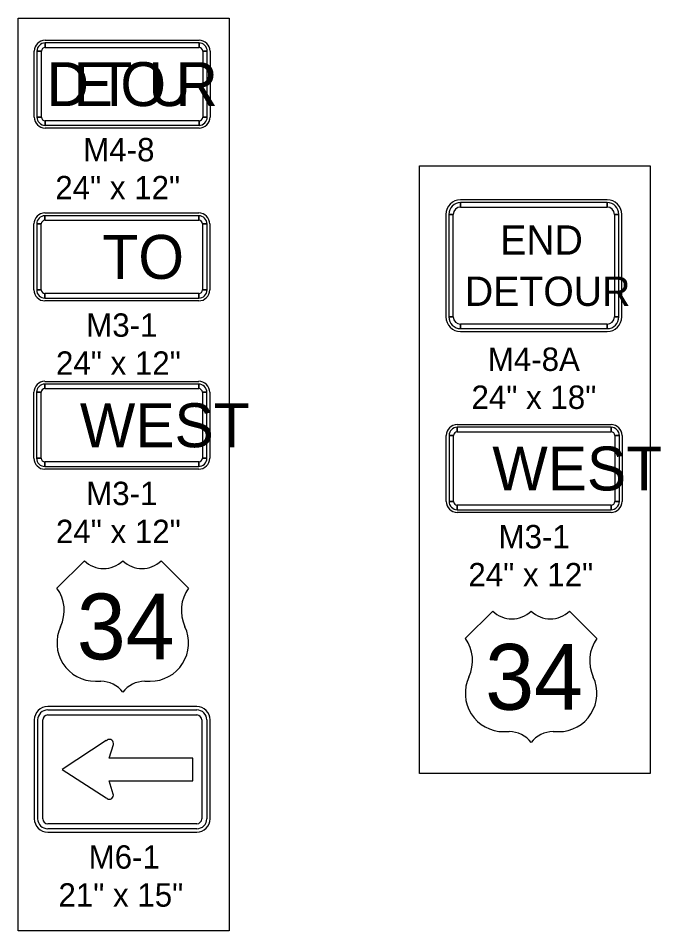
# Model space of a CAD drawing. Extents: x 10133 to 81668, y 6132 to 11018.
# Drawn here: x 11743.4 to 11963.1, y 6708.9 to 7021.1 of the extents above; entities that cross this region are included whole.
import ezdxf

# ---------------------------------------------------------------- set-up
doc = ezdxf.new("R2010")
doc.units = 0
for name, color, linetype in [('dsnTextFinalPlan', 7, 'Continuous'), ('Level 10', 7, 'Continuous'), ('Level 4', 7, 'Continuous'), ('Level 5', 7, 'Continuous')]:
    doc.layers.add(name, color=color, linetype=linetype)

msp = doc.modelspace()

# ---------------------------------------------------------------- linework, layer by layer
at = {"layer": 'dsnTextFinalPlan'}
for points in [[(11743.36, 7021.13), (11815.43, 7021.13), (11815.43, 6708.91), (11743.36, 6708.91)], [(11743.36, 7021.13), (11815.43, 7021.13), (11815.43, 6708.91), (11743.36, 6708.91)], [(11880.59, 6970.58), (11959.41, 6970.58), (11959.41, 6762.68), (11880.59, 6762.68)]]:
    msp.add_lwpolyline(points, close=True, dxfattribs=at)
at = {"layer": 'Level 10'}
for p, q in [((11752.57, 7013.62), (11805.18, 7013.62)), ((11752.57, 7013.62), (11805.18, 7013.62)), ((11752.57, 7011.12), (11752.57, 7012.68)), ((11752.57, 7011.12), (11752.57, 7012.68)), ((11805.18, 7012.68), (11805.18, 7011.12)), ((11805.18, 7012.68), (11805.18, 7011.12)), ((11748.81, 6987.31), (11748.81, 7009.86)), ((11748.81, 6987.31), (11748.81, 7009.86)), ((11749.75, 7009.86), (11751.32, 7009.86)), ((11749.75, 7009.86), (11751.32, 7009.86)), ((11806.43, 7009.86), (11808, 7009.86)), ((11806.43, 7009.86), (11808, 7009.86)), ((11808.94, 7009.86), (11808.94, 6987.31)), ((11808.94, 7009.86), (11808.94, 6987.31)), ((11751.32, 6987.31), (11749.75, 6987.31)), ((11751.32, 6987.31), (11749.75, 6987.31)), ((11752.57, 6984.5), (11752.57, 6986.06)), ((11752.57, 6984.5), (11752.57, 6986.06)), ((11805.18, 6986.06), (11805.18, 6984.5)), ((11805.18, 6986.06), (11805.18, 6984.5)), ((11808, 6987.31), (11806.43, 6987.31)), ((11808, 6987.31), (11806.43, 6987.31)), ((11805.18, 6983.56), (11752.57, 6983.56)), ((11805.18, 6983.56), (11752.57, 6983.56)), ((11944.74, 6959.04), (11894.63, 6959.04)), ((11894.63, 6956.53), (11894.63, 6958.04)), ((11944.74, 6958.04), (11894.63, 6958.04)), ((11894.63, 6958.04), (11894.63, 6956.53)), ((11894.63, 6956.53), (11944.74, 6956.53)), ((11944.74, 6956.53), (11944.74, 6958.04)), ((11944.74, 6958.04), (11944.74, 6956.53)), ((11752.48, 6954.5), (11805.09, 6954.5)), ((11752.48, 6954.5), (11805.09, 6954.5)), ((11752.48, 6952), (11752.48, 6953.56)), ((11752.48, 6952), (11752.48, 6953.56)), ((11805.09, 6953.56), (11805.09, 6952)), ((11805.09, 6953.56), (11805.09, 6952)), ((11889.62, 6954.03), (11889.62, 6918.95)), ((11890.63, 6954.03), (11890.63, 6918.95)), ((11892.13, 6954.03), (11890.63, 6954.03)), ((11890.63, 6954.03), (11892.13, 6954.03)), ((11892.13, 6918.95), (11892.13, 6954.03)), ((11947.25, 6954.03), (11948.75, 6954.03)), ((11947.25, 6954.03), (11947.25, 6918.95)), ((11948.75, 6954.03), (11947.25, 6954.03)), ((11948.75, 6918.95), (11948.75, 6954.03)), ((11949.75, 6918.95), (11949.75, 6954.03)), ((11748.72, 6928.19), (11748.72, 6950.74)), ((11748.72, 6928.19), (11748.72, 6950.74)), ((11749.66, 6950.74), (11751.22, 6950.74)), ((11749.66, 6950.74), (11751.22, 6950.74)), ((11806.34, 6950.74), (11807.91, 6950.74)), ((11806.34, 6950.74), (11807.91, 6950.74)), ((11808.85, 6950.74), (11808.85, 6928.19)), ((11808.85, 6950.74), (11808.85, 6928.19)), ((11751.22, 6928.19), (11749.66, 6928.19)), ((11751.22, 6928.19), (11749.66, 6928.19)), ((11752.48, 6925.38), (11752.48, 6926.94)), ((11752.48, 6925.38), (11752.48, 6926.94)), ((11805.09, 6926.94), (11805.09, 6925.38)), ((11805.09, 6926.94), (11805.09, 6925.38)), ((11807.91, 6928.19), (11806.34, 6928.19)), ((11807.91, 6928.19), (11806.34, 6928.19)), ((11805.09, 6924.44), (11752.48, 6924.44)), ((11805.09, 6924.44), (11752.48, 6924.44)), ((11890.63, 6918.95), (11892.13, 6918.95)), ((11892.13, 6918.95), (11890.63, 6918.95)), ((11947.25, 6918.95), (11948.75, 6918.95)), ((11948.75, 6918.95), (11947.25, 6918.95)), ((11944.74, 6916.45), (11894.63, 6916.45)), ((11894.63, 6916.45), (11894.63, 6914.94)), ((11894.63, 6914.94), (11894.63, 6916.45)), ((11944.74, 6916.45), (11944.74, 6914.94)), ((11944.74, 6914.94), (11944.74, 6916.45)), ((11894.63, 6914.94), (11944.74, 6914.94)), ((11894.63, 6913.94), (11944.74, 6913.94)), ((11752.45, 6896.89), (11805.07, 6896.89)), ((11752.45, 6896.89), (11805.07, 6896.89)), ((11752.45, 6894.39), (11752.45, 6895.95)), ((11752.45, 6894.39), (11752.45, 6895.95)), ((11805.07, 6895.95), (11805.07, 6894.39)), ((11805.07, 6895.95), (11805.07, 6894.39)), ((11748.7, 6870.59), (11748.7, 6893.14)), ((11748.7, 6870.59), (11748.7, 6893.14)), ((11749.64, 6893.14), (11751.2, 6893.14)), ((11749.64, 6893.14), (11751.2, 6893.14)), ((11806.32, 6893.14), (11807.89, 6893.14)), ((11806.32, 6893.14), (11807.89, 6893.14)), ((11808.82, 6893.14), (11808.82, 6870.59)), ((11808.82, 6893.14), (11808.82, 6870.59)), ((11893.49, 6882.11), (11946.1, 6882.11)), ((11889.73, 6855.8), (11889.73, 6878.35)), ((11890.67, 6878.35), (11892.24, 6878.35)), ((11893.49, 6879.6), (11893.49, 6881.17)), ((11946.1, 6881.17), (11946.1, 6879.6)), ((11947.35, 6878.35), (11948.92, 6878.35)), ((11949.86, 6878.35), (11949.86, 6855.8)), ((11751.2, 6870.59), (11749.64, 6870.59)), ((11751.2, 6870.59), (11749.64, 6870.59)), ((11752.45, 6867.77), (11752.45, 6869.33)), ((11752.45, 6867.77), (11752.45, 6869.33)), ((11805.07, 6869.33), (11805.07, 6867.77)), ((11805.07, 6869.33), (11805.07, 6867.77)), ((11807.89, 6870.59), (11806.32, 6870.59)), ((11807.89, 6870.59), (11806.32, 6870.59)), ((11805.07, 6866.83), (11752.45, 6866.83)), ((11805.07, 6866.83), (11752.45, 6866.83)), ((11892.24, 6855.8), (11890.67, 6855.8)), ((11893.49, 6852.98), (11893.49, 6854.55)), ((11946.1, 6854.55), (11946.1, 6852.98)), ((11948.92, 6855.8), (11947.35, 6855.8)), ((11946.1, 6852.04), (11893.49, 6852.04)), ((11804.39, 6785.6), (11753.42, 6785.6)), ((11804.39, 6785.6), (11753.42, 6785.6)), ((11753.43, 6784.46), (11804.4, 6784.46)), ((11753.43, 6784.46), (11804.4, 6784.46)), ((11753.43, 6782.74), (11804.4, 6782.74)), ((11753.43, 6782.74), (11804.4, 6782.74)), ((11748.84, 6781.02), (11748.84, 6747.24)), ((11748.84, 6781.02), (11748.84, 6747.24)), ((11750, 6747.24), (11750, 6781.02)), ((11750, 6747.24), (11750, 6781.02)), ((11751.72, 6747.24), (11751.72, 6781.02)), ((11751.72, 6747.24), (11751.72, 6781.02)), ((11806.12, 6781.02), (11806.12, 6747.24)), ((11806.12, 6781.02), (11806.12, 6747.24)), ((11807.84, 6781.02), (11807.84, 6747.24)), ((11807.84, 6781.02), (11807.84, 6747.24)), ((11808.97, 6747.24), (11808.97, 6781.02)), ((11808.97, 6747.24), (11808.97, 6781.02)), ((11804.4, 6745.52), (11753.43, 6745.52)), ((11804.4, 6745.52), (11753.43, 6745.52)), ((11753.42, 6742.66), (11804.39, 6742.66)), ((11753.42, 6742.66), (11804.39, 6742.66)), ((11804.4, 6743.8), (11753.43, 6743.8)), ((11804.4, 6743.8), (11753.43, 6743.8))]:
    msp.add_line(p, q, dxfattribs=at)
for points in [[(11805.18, 7012.68), (11752.57, 7012.68), (11752.57, 7011.12), (11805.18, 7011.12), (11805.18, 7012.68)], [(11805.18, 7012.68), (11752.57, 7012.68), (11752.57, 7011.12), (11805.18, 7011.12), (11805.18, 7012.68)], [(11749.75, 7009.86), (11749.75, 6987.31), (11751.32, 6987.31), (11751.32, 7009.86), (11749.75, 7009.86)], [(11749.75, 7009.86), (11749.75, 6987.31), (11751.32, 6987.31), (11751.32, 7009.86), (11749.75, 7009.86)], [(11808, 6987.31), (11808, 7009.86), (11806.43, 7009.86), (11806.43, 6987.31), (11808, 6987.31)], [(11808, 6987.31), (11808, 7009.86), (11806.43, 7009.86), (11806.43, 6987.31), (11808, 6987.31)], [(11752.57, 6984.5), (11805.18, 6984.5), (11805.18, 6986.06), (11752.57, 6986.06), (11752.57, 6984.5)], [(11752.57, 6984.5), (11805.18, 6984.5), (11805.18, 6986.06), (11752.57, 6986.06), (11752.57, 6984.5)], [(11805.09, 6953.56), (11752.48, 6953.56), (11752.48, 6952), (11805.09, 6952), (11805.09, 6953.56)], [(11805.09, 6953.56), (11752.48, 6953.56), (11752.48, 6952), (11805.09, 6952), (11805.09, 6953.56)], [(11749.66, 6950.74), (11749.66, 6928.19), (11751.22, 6928.19), (11751.22, 6950.74), (11749.66, 6950.74)], [(11749.66, 6950.74), (11749.66, 6928.19), (11751.22, 6928.19), (11751.22, 6950.74), (11749.66, 6950.74)], [(11807.91, 6928.19), (11807.91, 6950.74), (11806.34, 6950.74), (11806.34, 6928.19), (11807.91, 6928.19)], [(11807.91, 6928.19), (11807.91, 6950.74), (11806.34, 6950.74), (11806.34, 6928.19), (11807.91, 6928.19)], [(11752.48, 6925.38), (11805.09, 6925.38), (11805.09, 6926.94), (11752.48, 6926.94), (11752.48, 6925.38)], [(11752.48, 6925.38), (11805.09, 6925.38), (11805.09, 6926.94), (11752.48, 6926.94), (11752.48, 6925.38)], [(11805.07, 6895.95), (11752.45, 6895.95), (11752.45, 6894.39), (11805.07, 6894.39), (11805.07, 6895.95)], [(11805.07, 6895.95), (11752.45, 6895.95), (11752.45, 6894.39), (11805.07, 6894.39), (11805.07, 6895.95)], [(11749.64, 6893.14), (11749.64, 6870.59), (11751.2, 6870.59), (11751.2, 6893.14), (11749.64, 6893.14)], [(11749.64, 6893.14), (11749.64, 6870.59), (11751.2, 6870.59), (11751.2, 6893.14), (11749.64, 6893.14)], [(11807.89, 6870.59), (11807.89, 6893.14), (11806.32, 6893.14), (11806.32, 6870.59), (11807.89, 6870.59)], [(11807.89, 6870.59), (11807.89, 6893.14), (11806.32, 6893.14), (11806.32, 6870.59), (11807.89, 6870.59)], [(11890.67, 6878.35), (11890.67, 6855.8), (11892.24, 6855.8), (11892.24, 6878.35), (11890.67, 6878.35)], [(11946.1, 6881.17), (11893.49, 6881.17), (11893.49, 6879.6), (11946.1, 6879.6), (11946.1, 6881.17)], [(11948.92, 6855.8), (11948.92, 6878.35), (11947.35, 6878.35), (11947.35, 6855.8), (11948.92, 6855.8)], [(11752.45, 6867.77), (11805.07, 6867.77), (11805.07, 6869.33), (11752.45, 6869.33), (11752.45, 6867.77)], [(11752.45, 6867.77), (11805.07, 6867.77), (11805.07, 6869.33), (11752.45, 6869.33), (11752.45, 6867.77)], [(11893.49, 6852.98), (11946.1, 6852.98), (11946.1, 6854.55), (11893.49, 6854.55), (11893.49, 6852.98)]]:
    msp.add_lwpolyline(points, close=True, dxfattribs=at)
for points in [[(11773.38, 6773.95), (11758.39, 6764.13), (11773.38, 6754.34)], [(11773.38, 6773.95), (11758.39, 6764.13), (11773.38, 6754.34)], [(11775.85, 6755.67), (11774.49, 6760.25), (11803.01, 6760.25), (11803.01, 6768.01), (11774.49, 6768.01), (11775.88, 6772.58)], [(11775.85, 6755.67), (11774.49, 6760.25), (11803.01, 6760.25), (11803.01, 6768.01), (11774.49, 6768.01), (11775.88, 6772.58)]]:
    msp.add_lwpolyline(points, dxfattribs=at)
for centre, radius, start, end in [((11752.57, 7009.86), 3.76, 90, 180), ((11752.57, 7009.86), 3.76, 90, 180), ((11752.57, 7009.86), 2.82, 90.0002, 179.9998), ((11752.57, 7009.86), 2.82, 90.0002, 179.9998), ((11805.18, 7009.86), 3.76, 0, 90), ((11805.18, 7009.86), 3.76, 0, 90), ((11805.18, 7009.86), 2.82, 0, 90.0002), ((11805.18, 7009.86), 2.82, 0, 90.0002), ((11752.57, 7009.86), 1.25, 90.0002, 179.9998), ((11752.57, 7009.86), 1.25, 90.0002, 179.9998), ((11805.18, 7009.86), 1.25, 0, 90.0002), ((11805.18, 7009.86), 1.25, 0, 90.0002), ((11752.57, 6987.31), 3.76, 180, 270), ((11752.57, 6987.31), 3.76, 180, 270), ((11752.57, 6987.31), 2.82, 179.9998, 270.0001), ((11752.57, 6987.31), 2.82, 179.9998, 270.0001), ((11752.57, 6987.31), 1.25, 179.9998, 270.0001), ((11752.57, 6987.31), 1.25, 179.9998, 270.0001), ((11805.18, 6987.31), 2.82, 270.0001, 0.0003), ((11805.18, 6987.31), 1.25, 270.0001, 0.0003), ((11805.18, 6987.31), 3.76, 270, 359.9911), ((11805.18, 6987.31), 2.82, 270.0001, 0.0003), ((11805.18, 6987.31), 1.25, 270.0001, 0.0003), ((11805.18, 6987.31), 3.76, 270, 359.9911), ((11894.63, 6954.03), 5.01, 90, 180), ((11894.63, 6954.03), 4.01, 90, 180), ((11894.63, 6954.03), 2.51, 90, 180), ((11944.74, 6954.03), 5.01, 0, 90), ((11944.74, 6954.03), 4.01, 0, 90), ((11944.74, 6954.03), 2.51, 0, 90), ((11752.48, 6950.74), 3.76, 90, 180), ((11752.48, 6950.74), 3.76, 90, 180), ((11752.48, 6950.74), 2.82, 90.0002, 179.9998), ((11752.48, 6950.74), 2.82, 90.0002, 179.9998), ((11805.09, 6950.74), 3.76, 0, 90), ((11805.09, 6950.74), 3.76, 0, 90), ((11805.09, 6950.74), 2.82, 0, 90.0002), ((11805.09, 6950.74), 2.82, 0, 90.0002), ((11752.48, 6950.74), 1.25, 90.0002, 179.9998), ((11752.48, 6950.74), 1.25, 90.0002, 179.9998), ((11805.09, 6950.74), 1.25, 0, 90.0002), ((11805.09, 6950.74), 1.25, 0, 90.0002), ((11752.48, 6928.19), 3.76, 180, 270), ((11752.48, 6928.19), 3.76, 180, 270), ((11752.48, 6928.19), 2.82, 179.9998, 270.0001), ((11752.48, 6928.19), 2.82, 179.9998, 270.0001), ((11752.48, 6928.19), 1.25, 179.9998, 270.0001), ((11752.48, 6928.19), 1.25, 179.9998, 270.0001), ((11805.09, 6928.19), 2.82, 270.0001, 0.0003), ((11805.09, 6928.19), 1.25, 270.0001, 0.0003), ((11805.09, 6928.19), 3.76, 270, 359.9911), ((11805.09, 6928.19), 2.82, 270.0001, 0.0003), ((11805.09, 6928.19), 1.25, 270.0001, 0.0003), ((11805.09, 6928.19), 3.76, 270, 359.9911), ((11894.63, 6918.95), 5.01, 180, 270), ((11894.63, 6918.95), 4.01, 180, 270), ((11894.63, 6918.95), 2.51, 180, 270), ((11944.74, 6918.95), 2.51, 270, 0), ((11944.74, 6918.95), 4.01, 270, 360), ((11944.74, 6918.95), 5.01, 270, 0), ((11752.45, 6893.14), 3.76, 90, 180), ((11752.45, 6893.14), 3.76, 90, 180), ((11752.45, 6893.14), 2.82, 90.0002, 179.9998), ((11752.45, 6893.14), 2.82, 90.0002, 179.9998), ((11752.45, 6893.14), 1.25, 90.0002, 179.9998), ((11752.45, 6893.14), 1.25, 90.0002, 179.9998), ((11805.07, 6893.14), 3.76, 0, 90), ((11805.07, 6893.14), 3.76, 0, 90), ((11805.07, 6893.14), 2.82, 0, 90.0002), ((11805.07, 6893.14), 2.82, 0, 90.0002), ((11805.07, 6893.14), 1.25, 0, 90.0002), ((11805.07, 6893.14), 1.25, 0, 90.0002), ((11893.49, 6878.35), 3.76, 90, 180), ((11946.1, 6878.35), 3.76, 0, 90), ((11893.49, 6878.35), 2.82, 90.0002, 179.9998), ((11893.49, 6878.35), 1.25, 90.0002, 179.9998), ((11946.1, 6878.35), 2.82, 0, 90.0002), ((11946.1, 6878.35), 1.25, 0, 90.0002), ((11752.45, 6870.59), 3.76, 180, 270), ((11752.45, 6870.59), 3.76, 180, 270), ((11752.45, 6870.59), 2.82, 179.9998, 270.0001), ((11752.45, 6870.59), 2.82, 179.9998, 270.0001), ((11752.45, 6870.59), 1.25, 179.9998, 270.0001), ((11752.45, 6870.59), 1.25, 179.9998, 270.0001), ((11805.07, 6870.59), 2.82, 270.0001, 0.0003), ((11805.07, 6870.59), 1.25, 270.0001, 0.0003), ((11805.07, 6870.59), 3.76, 270, 359.9911), ((11805.07, 6870.59), 2.82, 270.0001, 0.0003), ((11805.07, 6870.59), 1.25, 270.0001, 0.0003), ((11805.07, 6870.59), 3.76, 270, 359.9911), ((11893.49, 6855.8), 3.76, 180, 270), ((11893.49, 6855.8), 2.82, 179.9998, 270.0001), ((11893.49, 6855.8), 1.25, 179.9998, 270.0001), ((11946.1, 6855.8), 2.82, 270.0001, 0.0003), ((11946.1, 6855.8), 1.25, 270.0001, 0.0003), ((11946.1, 6855.8), 3.76, 270, 359.9911), ((11753.42, 6781.02), 4.58, 90, 180), ((11753.42, 6781.02), 4.58, 90, 180), ((11804.39, 6781.02), 4.58, 360, 90), ((11804.39, 6781.02), 4.58, 360, 90), ((11753.43, 6781.02), 3.44, 90, 180), ((11753.43, 6781.02), 3.44, 90, 180), ((11753.43, 6781.02), 1.72, 90, 180), ((11753.43, 6781.02), 1.72, 90, 180), ((11804.4, 6781.02), 3.44, 0, 90), ((11804.4, 6781.02), 3.44, 0, 90), ((11804.4, 6781.02), 1.72, 0, 90), ((11804.4, 6781.02), 1.72, 0, 90), ((11694.93, 6893.7), 143.16, 303.2286, 303.3891), ((11694.93, 6893.7), 143.16, 303.2286, 303.3891), ((11774.51, 6772.97), 1.43, 344.0309, 123.3891), ((11774.51, 6772.97), 1.43, 344.0309, 123.3891), ((11695.11, 6634.47), 143.16, 56.6896, 56.857), ((11695.11, 6634.47), 143.16, 56.6896, 56.857), ((11774.51, 6755.29), 1.4, 236.6896, 15.9691), ((11774.51, 6755.29), 1.4, 236.6896, 15.9691), ((11753.42, 6747.24), 4.58, 180, 270), ((11753.42, 6747.24), 4.58, 180, 270), ((11753.43, 6747.24), 3.44, 180, 270), ((11753.43, 6747.24), 3.44, 180, 270), ((11753.43, 6747.24), 1.72, 180, 270), ((11753.43, 6747.24), 1.72, 180, 270), ((11804.39, 6747.24), 4.58, 270, 0), ((11804.39, 6747.24), 4.58, 270, 0), ((11804.4, 6747.24), 3.44, 270, 0), ((11804.4, 6747.24), 1.72, 270, 0), ((11804.4, 6747.24), 3.44, 270, 0), ((11804.4, 6747.24), 1.72, 270, 0)]:
    msp.add_arc(centre, radius, start, end, dxfattribs=at)
at = {"layer": 'Level 4'}
for p, q in [((11765.97, 6835.52), (11756.6, 6826.14)), ((11765.97, 6835.52), (11756.6, 6826.14)), ((11801.6, 6826.14), (11792.22, 6835.52)), ((11801.6, 6826.14), (11792.22, 6835.52)), ((11905.62, 6818.28), (11896.24, 6808.91)), ((11941.24, 6808.91), (11931.87, 6818.28)), ((11769.72, 6794.27), (11771.6, 6794.27)), ((11769.72, 6794.27), (11771.6, 6794.27)), ((11786.6, 6794.27), (11788.47, 6794.27)), ((11786.6, 6794.27), (11788.47, 6794.27)), ((11909.37, 6777.03), (11911.24, 6777.03)), ((11926.24, 6777.03), (11928.12, 6777.03))]:
    msp.add_line(p, q, dxfattribs=at)
for centre, radius, start, end in [((11772.53, 6842.21), 9.38, 225.5729, 314.4272), ((11772.53, 6842.21), 9.38, 225.5729, 314.4272), ((11785.66, 6842.21), 9.38, 225.5729, 314.4272), ((11785.66, 6842.21), 9.38, 225.5729, 314.4272), ((11745.93, 6818.49), 13.13, 334.9895, 35.6629), ((11745.93, 6818.49), 13.13, 334.9895, 35.6629), ((11812.26, 6818.49), 13.13, 144.3372, 205.01), ((11812.26, 6818.49), 13.13, 144.3372, 205.01), ((11912.18, 6824.98), 9.38, 225.5729, 314.4272), ((11925.31, 6824.98), 9.38, 225.5729, 314.4272), ((11769.72, 6807.39), 13.13, 154.9897, 270.0001), ((11769.72, 6807.39), 13.13, 154.9897, 270.0001), ((11788.47, 6807.39), 13.13, 270.0001, 25.0104), ((11788.47, 6807.39), 13.13, 270.0001, 25.0104), ((11885.58, 6801.26), 13.13, 334.9895, 35.6629), ((11951.91, 6801.26), 13.13, 144.3372, 205.01), ((11771.6, 6784.89), 9.38, 36.8699, 90.0002), ((11771.6, 6784.89), 9.38, 36.8699, 90.0002), ((11786.6, 6784.89), 9.38, 90.0002, 143.13), ((11786.6, 6784.89), 9.38, 90.0002, 143.13), ((11909.37, 6790.16), 13.13, 154.9897, 270.0001), ((11928.12, 6790.16), 13.13, 270.0001, 25.0104), ((11911.24, 6767.66), 9.38, 36.8699, 90.0002), ((11926.24, 6767.66), 9.38, 90.0002, 143.13)]:
    msp.add_arc(centre, radius, start, end, dxfattribs=at)

# ---------------------------------------------------------------- texts
at = {"layer": 'Level 10'}
for s, height, p in [('O', 15.03, (11778.28, 6991.07)), ('O', 15.03, (11778.28, 6991.07)), ('D', 15.03, (11753.06, 6991.07)), ('D', 15.03, (11753.06, 6991.07)), ('E', 15.03, (11762.29, 6991.07)), ('E', 15.03, (11762.29, 6991.07)), ('T', 15.03, (11770.07, 6991.07)), ('T', 15.03, (11770.07, 6991.07)), ('U', 15.03, (11787.87, 6991.07)), ('U', 15.03, (11787.87, 6991.07)), ('R', 15.03, (11797.11, 6991.07)), ('R', 15.03, (11797.11, 6991.07)), ('END', 10.021, (11908.16, 6940.25)), ('TO', 15.032, (11772.14, 6931.95)), ('TO', 15.032, (11772.14, 6931.95)), ('DETOUR', 10.021, (11896.11, 6922.71)), ('WEST', 15.032, (11764.43, 6874.35)), ('WEST', 15.032, (11905.47, 6859.56))]:
    msp.add_text(s, height=height, dxfattribs=at).set_placement(p)
at = {"layer": 'Level 4'}
for p in [(11763.39, 6801.77), (11763.39, 6801.77), (11903.04, 6784.53)]:
    msp.add_text('34', height=22.5, dxfattribs=at).set_placement(p)
at = {"layer": 'Level 5'}
for s, p in [('M4-8', (11765.58, 6972.17)), ('M4-8', (11765.58, 6972.17)), ('24" x 12"', (11756.02, 6959.17)), ('24" x 12"', (11756.02, 6959.17)), ('M3-1', (11766.6, 6912.14)), ('M3-1', (11766.6, 6912.14)), ('24" x 12"', (11756.27, 6899.14)), ('24" x 12"', (11756.27, 6899.14)), ('M4-8A', (11903.92, 6900.46)), ('24" x 18"', (11898.35, 6887.46)), ('M3-1', (11766.58, 6854.54)), ('M3-1', (11766.58, 6854.54)), ('24" x 12"', (11756.25, 6841.54)), ('24" x 12"', (11756.25, 6841.54)), ('M3-1', (11907.61, 6839.75)), ('24" x 12"', (11897.28, 6826.75)), ('M6-1', (11767.43, 6730.15)), ('M6-1', (11767.43, 6730.15)), ('21" x 15"', (11757.1, 6717.15)), ('21" x 15"', (11757.1, 6717.15))]:
    msp.add_text(s, height=8, dxfattribs=at).set_placement(p)

doc.saveas('drawing.dxf')
